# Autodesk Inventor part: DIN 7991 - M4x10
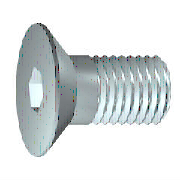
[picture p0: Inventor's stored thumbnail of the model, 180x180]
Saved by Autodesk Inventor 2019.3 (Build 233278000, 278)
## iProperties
Created: 2018-01
Part Number: DIN 7991 - M4x10
Material: Ocel, měkká
Description: Šrouby se zapuštěnou hlavou s vnitřním šestihranem
Document SubType Name: Modeling
Standard: DIN 7991
Designer: B-hon
Standards Organization: DIN
Language: cs-CZ
Size Designation: M4x10
Categories: <MemberInstance><Categories><Category DisplayName="Spojovací materiál" InternalName="e4da775c-781d-43d5-af7c-5136215cf5a6" Mnemonic="FSTN"><Category DisplayName
Density: 7.85 g/cm^3
Appearance: Pololeštěná
IsCustomPart: 0
Author: B-hon
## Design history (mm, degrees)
node "WorkPoint1"
sketch "Náčrt2"
  geometry: L1 (-2, -10)-(0, -10); L2 (-2, -2.3)-(-2, -10); L3 (-4, -0.3)-(-2, -2.3); L4 (-4, 0)-(-4, -0.3); L5 (0, 0)-(-4, 0); L6 (0, -10)-(0, 0); L7 (0, -10)-(0, 0); L8 (0, -12)-(0, 2) reference; L9 (0.8, 0)-(-4.8, 0) reference
  constraints: 14 end point, 3 vertical, 2 horizontal
  dimensions: "d3" = 4 distance of L5.start L4.start (= 0.5 x dk); "d5" = 2 distance of L1.start L1.end (= 0.5 x NND); "d7" = 10 distance of L1.end L5.start (= NLG); "ParC" = 0.3 distance of L4.start L3.start; "d22" = 0 distance between parallel lines of L8 L6; "d23" = 0 distance between parallel lines of L9 L5; "d43" = 45 deg angle of L6 L3 (= 0.5 x ang)
node "MSC_A1"
node "MSC_PF1"
node "MSC_PT1"
body "Solid1"
node "Náčrt1"
revolve "Rotace1" stored, may be unused: angle "d8" = 360 deg
sketch "Náčrt3"
  geometry: L1 (-1.25, 0.722)-(-1.25, -0.722); L2 (0, 1.443)-(-1.25, 0.722); L3 (1.25, 0.722)-(0, 1.443); L4 (1.25, -0.722)-(1.25, 0.722); L5 (0, -1.443)-(1.25, -0.722); L6 (-1.25, -0.722)-(0, -1.443); C1 r 1.25 at (0, 0); C2 r 2 at (0, 0) reference
  constraints: 12 end point, 6 tangent, 2 parallel, 2 vertical, 1 centre point, 1 concentric
  dimensions: "d11" = 2.5 diameter of C1 (= ParS); "d13" = 120 deg angle of L1 L2; "d15" = 120 deg angle of L6 L1
extrude "Vysunutí1" cut sketch "Náčrt3" distance "d16" = 1.8 (= ParT); taper "d17" = 0 deg
fillet "Zaoblení1" dims "d18" = 0.2 (= r)
chamfer "Zkosení1" distance "d19" = 0.35 (= 0.5 x PTC); stored, may be unused: angle "d20" = 45 deg, second distance "d39" = 0.35 (= 0.5 x PTC)
feature "Závit1" dims "d35" = 0, "b" = 6.3
other parameters: "NND" = 4 [user parameter; used in 2 equation terms], "PTC" = 0.7 [user parameter; used in 2 equation terms], "dk" = 8 [user parameter; used in 1 equation term], "ParK" = 2.3 [user parameter], "ParS" = 2.5 [user parameter; used in 1 equation term], "ParT" = 1.8 [user parameter; used in 1 equation term], "r" = 0.2 [user parameter; used in 1 equation term], "NLG" = 10 [user parameter; used in 1 equation term], "d0" = 45 deg (derived), "d2" = 3 (derived), "d4" = 1.5 (derived), "d6" = 8 (derived), "d9" = 0, "d10" = 2 (derived), "d12" = 120 deg (derived), "d14" = 120 deg (derived), "d37" = 0, "d38" = 0, "d40" = 0, "d41" = 0, "d42" = 0, "ang" = 90 deg [user parameter; used in 1 equation term], "THREADDIA" = 4 (= NND) [user parameter]
